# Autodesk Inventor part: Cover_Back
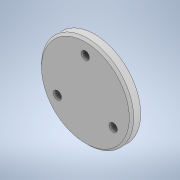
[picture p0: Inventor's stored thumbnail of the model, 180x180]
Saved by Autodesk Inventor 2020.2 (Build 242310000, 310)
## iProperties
Created: 2019-12
Part Number: Cover_Back
Material: Generic
Document SubType Name: Modeling
Designer: Patrick Everitt
Density: 1 g/cm^3
Appearance: Default
Author: Patrick Everitt
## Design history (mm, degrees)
sketch "Sketch1"
  geometry: C1 r 31.75 at (0, 0); 4 further points
  constraints: 1 centre point, 1 coincident
  dimensions: "d0" = 63.5 diameter of C1; "d1" = 22.225 distance of point (0, 22.225) point (0, 0); "d2" = 22.225 distance of point (0, 0) point (-19.247, -11.112) (= d1); "d3" = 22.225 distance of point (0, 0) point (19.247, -11.112) (= d1); "d4" = 120 deg dimension on point (0, 0) point (0, 22.225) point (19.247, -11.112); "d5" = 120 deg dimension on point (0, 0) point (0, 22.225) point (-19.247, -11.112) (= d4)
extrude "Extrusion1" new body sketch "Sketch1" distance "d6" = 6.35; taper "d7" = 0 deg
hole "Hole1" sketch "Sketch1" diameter "d8" = 5.588; stored, may be unused: countersink angle "d12" = 82 deg, drill point angle "d14" = 118 deg; dims "d9" = 19.05, "d10" = 9.525, "d11" = 6.35, "d13" = 25.4
chamfer "Chamfer1" distance "d15" = 1.524; stored, may be unused: second distance "d16" = 3.175, angle "d17" = 45 deg
body "Solid1"
